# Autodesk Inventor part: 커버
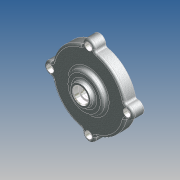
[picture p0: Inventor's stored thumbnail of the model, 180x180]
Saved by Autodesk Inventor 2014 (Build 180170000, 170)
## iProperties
Created: 2012-05
Part Number: 커버
Document SubType Name: 모델링
Designer: SeoGD™
Material: 알루미늄 6061
Density: 2.71 g/cm^3
Appearance: 알루미늄 캐스트
Mass: 196.657 g
Surface Area: 278.607 cm^2
Volume: 72.5671 cm^3
변환 표준: STEP AP214IS
파일 이름: C:\Users\SeoGD\Desktop\?쒗뿕\而ㅻ쾭-1.stp
전처리기: Build: 253, Release: 2010 SP1 - Date: Wed 07/29/2009
전송 단위: 밀리미터
불확실성: 0.01
Author: SeoGD™
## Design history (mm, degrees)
sketch "스케치1"
  geometry: L1 (0, 0)-(0, 26); L2 (50, 0)-(50, 15); L3 (50, 15)-(25, 15); L4 (25, 15)-(25, 21); L5 (25, 21)-(15, 21); L6 (15, 21)-(13.66, 26); L7 (13.66, 26)-(10, 26); L8 (50, 0)-(45, 0); L9 (45, 0)-(45, 10); L10 (45, 10)-(14.5, 10); L11 (14.5, 10)-(13.266, 3); L12 (13.266, 3)-(11, 3); L13 (11, 3)-(11, 16); L14 (11, 16)-(7.5, 16); L15 (7.5, 16)-(7.5, 19); L16 (7.5, 19)-(10, 19); L17 (10, 19)-(10, 26)
  constraints: 34 end point, 10 parallel, 2 perpendicular, 2 point on line, 1 vertical
  dimensions: "d11" = 100 diameter of L2 L1; "d12" = 22 diameter of L13 L1; "d13" = 90 diameter of L9 L1; "d14" = 15 distance between parallel lines of L3 L8; "d15" = 10 distance between parallel lines of L8 L10; "d16" = 29 diameter of L10.end L1; "d17" = 100 deg angle of L11 L10; "d18" = 7 distance between parallel lines of L12 L10; "d19" = 13 distance between parallel lines of L14 L12; "d20" = 3 distance between parallel lines of L16 L14; "d21" = 15 diameter of L15 L1; "d22" = 20 diameter of L17 L1; "d23" = 30 diameter of L5.end L1; "d24" = 6 distance between parallel lines of L5 L3; "d25" = 50 diameter of L4 L1; "d26" = 105 deg angle of L5 L6; "d50" = 26 distance of L1.start L1.end
revolve "회전1" sketch "스케치1" stored, may be unused: angle "d27" = 90 deg
sketch "스케치2" dims "d29" = 104
  geometry: A1 r 8.5 centre (0, 52) between (8.074, 49.344) and (-8.074, 49.344); A2 r 50 centre (0, 0) between (-8.074, 49.344) and (8.074, 49.344) reference; 2 further points
  constraints: 4 point on circle, 2 vertical alignment, 1 centre point, 1 coincident, 2 other
  dimensions: "d28" = 17 diameter of A1
extrude "돌출1" join sketch "스케치2" stored distance "d30" = 10; taper "d31" = 0 deg
fillet "모깎기3" dims "d32" = 3
fillet "모깎기4" dims "d45" = 3, "d46" = 0.2
chamfer "모따기1" distance "d47" = 1; stored, may be unused: second distance "d48" = 2, angle "d49" = 45 deg
hole "구멍2" diameter "d38" = 5.5; stored, may be unused: countersink angle "d42" = 90 deg, drill point angle "d44" = 118 deg; dims "d36" = 10, "d37" = 10, "d39" = 6, "d40" = 9.5, "d41" = 5.4, "d43" = 8
node "솔리드1"
node "솔리드 본체"
node "곡면 본체"
pattern_circular "원형 패턴1" dims angle "d34" = 360 deg
pattern_circular "원형 패턴2" dims angle "d52" = 360 deg
node "솔리드2"
